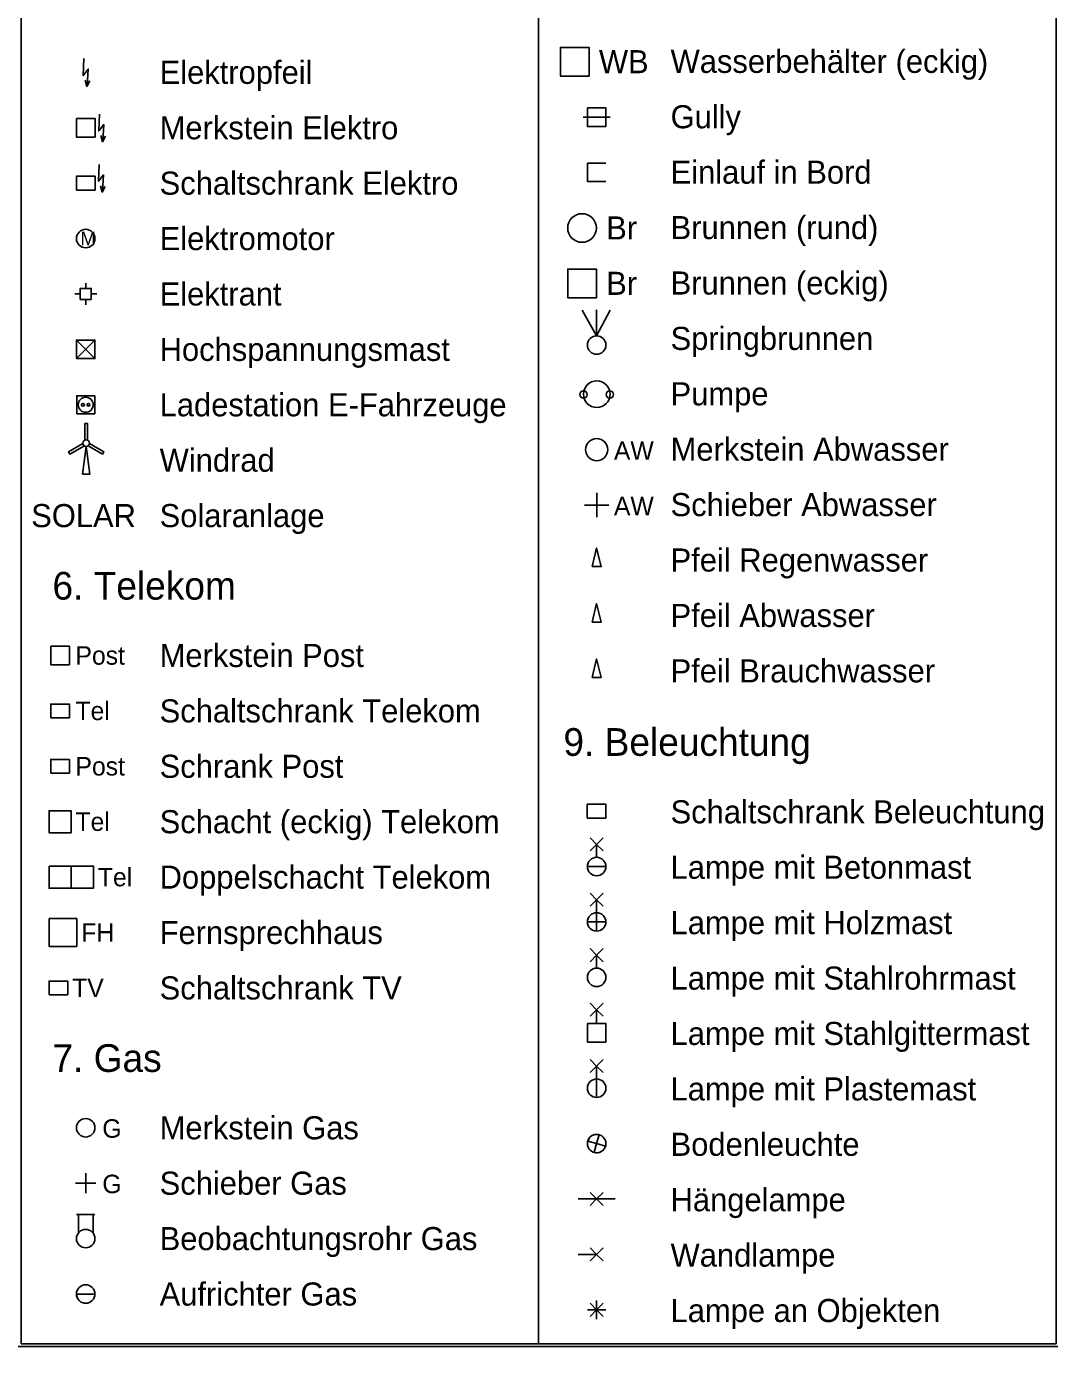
# Model space of a CAD drawing. Extents: x 679244 to 679420, y 5639809 to 5639932.
# Drawn here: x 679332.6 to 679387.9, y 5639808.5 to 5639880 of the extents above; entities that cross this region are included whole.
import ezdxf

# ---------------------------------------------------------------- set-up
doc = ezdxf.new("R2010")
doc.units = 0
for name, color, linetype in [('Aufrichter_gas', 7, 'Continuous'), ('Beobrohr_gas', 7, 'Continuous'), ('Bodenleuchte', 7, 'Continuous'), ('Brunnen_eckig', 7, 'Continuous'), ('Brunnen_rund', 7, 'Continuous'), ('Default', 7, 'Continuous'), ('Doppelschacht_tel', 7, 'Continuous'), ('Einlauf', 7, 'Continuous'), ('Elektrant', 7, 'Continuous'), ('Elektromotor', 7, 'Continuous'), ('Elektropfeil', 7, 'Continuous'), ('Fernsprechhaus', 7, 'Continuous'), ('Gully', 7, 'Continuous'), ('Haengelampe', 7, 'Continuous'), ('Hochspannungsmast', 7, 'Continuous'), ('Ladestation', 7, 'Continuous'), ('Lampe_betonmast', 7, 'Continuous'), ('Lampe_holzmast', 7, 'Continuous'), ('Lampe_plastemast', 7, 'Continuous'), ('Lampe_stahlgittermast', 7, 'Continuous'), ('Lampe_stahlrohrmast', 7, 'Continuous'), ('Merkstein_abwasser', 7, 'Continuous'), ('Merkstein_elektro', 7, 'Continuous'), ('Merkstein_gas', 7, 'Continuous'), ('Merkstein_post', 7, 'Continuous'), ('Objektlampe', 7, 'Continuous'), ('Pfeil_abwasser', 7, 'Continuous'), ('Pfeil_brauchwasser', 7, 'Continuous'), ('Pfeil_regenwasser', 7, 'Continuous'), ('Pumpe', 7, 'Continuous'), ('Rahmen_1', 7, 'Continuous'), ('Schacht_tel', 7, 'Continuous'), ('Schaltschrank_elektro', 7, 'Continuous'), ('Schaltschrank_leucht', 7, 'Continuous'), ('Schaltschrank_tel', 7, 'Continuous'), ('Schaltschrank_tv', 7, 'Continuous'), ('Schieber_abwasser', 7, 'Continuous'), ('Schieber_gas', 7, 'Continuous'), ('Schrank_post', 7, 'Continuous'), ('Schrift_aw', 7, 'Continuous'), ('Schrift_fh', 7, 'Continuous'), ('Schrift_g', 7, 'Continuous'), ('Schrift_post', 7, 'Continuous'), ('Schrift_tel', 7, 'Continuous'), ('Schrift_tv', 7, 'Continuous'), ('Schrift_wb', 7, 'Continuous'), ('Solar', 7, 'Continuous'), ('Springbrunnen', 7, 'Continuous'), ('Wandlampe', 7, 'Continuous'), ('Wasserbehaelter_eckig', 7, 'Continuous'), ('Windrad', 7, 'Continuous')]:
    doc.layers.add(name, color=color, linetype=linetype)

msp = doc.modelspace()

# ---------------------------------------------------------------- linework, layer by layer
at = {"layer": 'Aufrichter_gas'}
msp.add_lwpolyline([(679336.283, 5639811.362), (679336.282, 5639811.362), (679336.263, 5639811.362), (679335.783, 5639811.362), (679335.283, 5639811.362), (679335.283, 5639811.355)], dxfattribs=at)
msp.add_circle((679335.783, 5639811.362), 0.5, dxfattribs=at)
msp.add_arc((679335.783, 5639811.362), 0.5, 180.8, 0, dxfattribs=at)
at = {"layer": 'Beobrohr_gas'}
for p, q in [((679335.283, 5639815.664), (679336.283, 5639815.666)), ((679335.386, 5639815.664), (679335.386, 5639814.666)), ((679336.18, 5639815.666), (679336.18, 5639814.666))]:
    msp.add_line(p, q, dxfattribs=at)
msp.add_circle((679335.783, 5639814.362), 0.5, dxfattribs=at)
at = {"layer": 'Bodenleuchte'}
for points in [[(679362.945, 5639819.639), (679363.427, 5639819.506), (679363.56, 5639819.988)], [(679363.909, 5639819.373), (679363.427, 5639819.506), (679363.294, 5639819.024)]]:
    msp.add_lwpolyline(points, dxfattribs=at)
msp.add_circle((679363.427, 5639819.506), 0.5, dxfattribs=at)
for start, end in [(74.56981, 164.56981), (254.56981, 344.56981)]:
    msp.add_arc((679363.427, 5639819.506), 0.5, start, end, dxfattribs=at)
at = {"layer": 'Brunnen_eckig'}
msp.add_line((679362.635, 5639866.078), (679362.635, 5639866.078), dxfattribs=at)
msp.add_lwpolyline([(679363.41, 5639865.303), (679363.41, 5639866.853), (679361.86, 5639866.853), (679361.86, 5639865.303)], close=True, dxfattribs=at)
at = {"layer": 'Brunnen_rund'}
msp.add_line((679362.635, 5639869.078), (679362.635, 5639869.078), dxfattribs=at)
msp.add_circle((679362.635, 5639869.078), 0.775, dxfattribs=at)
at = {"layer": 'Default'}
for points in [[(679332.286, 5639808.666), (679360.286, 5639808.666), (679360.286, 5639928.666), (679332.286, 5639928.666)], [(679360.286, 5639808.666), (679388.286, 5639808.666), (679388.286, 5639928.666), (679360.286, 5639928.666)]]:
    msp.add_lwpolyline(points, close=True, dxfattribs=at)
at = {"layer": 'Doppelschacht_tel'}
for points in [[(679333.801, 5639834.534), (679335.001, 5639834.534), (679335.001, 5639833.334), (679333.801, 5639833.334)], [(679335.001, 5639834.534), (679336.201, 5639834.534), (679336.201, 5639833.334), (679335.001, 5639833.334)]]:
    msp.add_lwpolyline(points, close=True, dxfattribs=at)
at = {"layer": 'Einlauf'}
msp.add_lwpolyline([(679363.932, 5639872.587), (679362.932, 5639872.587), (679362.932, 5639871.587), (679363.932, 5639871.587)], dxfattribs=at)
at = {"layer": 'Elektrant'}
for p, q in [((679335.783, 5639866.1), (679335.783, 5639865.803)), ((679335.189, 5639865.506), (679335.486, 5639865.506)), ((679336.377, 5639865.506), (679336.08, 5639865.506)), ((679335.783, 5639864.912), (679335.783, 5639865.209))]:
    msp.add_line(p, q, dxfattribs=at)
msp.add_lwpolyline([(679336.08, 5639865.209), (679335.486, 5639865.209), (679335.486, 5639865.803), (679336.08, 5639865.803)], close=True, dxfattribs=at)
at = {"layer": 'Elektromotor'}
msp.add_circle((679335.783, 5639868.506), 0.5, dxfattribs=at)
at = {"layer": 'Elektropfeil'}
for points in [[(679335.681, 5639878.247), (679335.646, 5639877.333), (679335.92, 5639877.679), (679335.862, 5639876.785)], [(679336.01, 5639877.045), (679335.852, 5639876.748), (679335.755, 5639877.078)], [(679336.521, 5639875.247), (679336.486, 5639874.333), (679336.76, 5639874.679), (679336.702, 5639873.785)], [(679336.85, 5639874.045), (679336.692, 5639873.748), (679336.595, 5639874.078)], [(679336.511, 5639872.521), (679336.476, 5639871.607), (679336.75, 5639871.953), (679336.692, 5639871.059)], [(679336.84, 5639871.319), (679336.682, 5639871.022), (679336.585, 5639871.352)]]:
    msp.add_lwpolyline(points, dxfattribs=at)
at = {"layer": 'Fernsprechhaus'}
msp.add_lwpolyline([(679333.801, 5639831.684), (679335.301, 5639831.684), (679335.301, 5639830.184), (679333.801, 5639830.184)], close=True, dxfattribs=at)
at = {"layer": 'Gully'}
msp.add_line((679362.703, 5639875.078), (679364.15, 5639875.078), dxfattribs=at)
msp.add_lwpolyline([(679362.927, 5639875.578), (679363.927, 5639875.578), (679363.927, 5639874.578), (679362.927, 5639874.578)], close=True, dxfattribs=at)
at = {"layer": 'Haengelampe'}
for p, q in [((679363.073, 5639816.86), (679363.427, 5639816.506)), ((679363.781, 5639816.86), (679363.427, 5639816.506)), ((679363.427, 5639816.506), (679362.426, 5639816.506)), ((679363.073, 5639816.152), (679363.427, 5639816.506)), ((679363.781, 5639816.152), (679363.427, 5639816.506)), ((679364.428, 5639816.506), (679363.427, 5639816.506))]:
    msp.add_line(p, q, dxfattribs=at)
at = {"layer": 'Hochspannungsmast'}
for p, q in [((679335.283, 5639863.006), (679336.283, 5639862.006)), ((679336.283, 5639863.006), (679335.283, 5639862.006))]:
    msp.add_line(p, q, dxfattribs=at)
msp.add_lwpolyline([(679335.283, 5639862.006), (679336.283, 5639862.006), (679336.283, 5639863.006), (679335.283, 5639863.006)], close=True, dxfattribs=at)
at = {"layer": 'Ladestation'}
msp.add_lwpolyline([(679335.297, 5639859.021), (679336.268, 5639859.021), (679336.268, 5639859.992), (679335.297, 5639859.992)], close=True, dxfattribs=at)
for centre, radius in [((679335.783, 5639859.506), 0.407), ((679335.633, 5639859.506), 0.0762), ((679335.933, 5639859.506), 0.0762)]:
    msp.add_circle(centre, radius, dxfattribs=at)
at = {"layer": 'Lampe_betonmast'}
for p, q in [((679363.073, 5639836.058), (679363.427, 5639835.704)), ((679363.781, 5639836.058), (679363.427, 5639835.704)), ((679363.073, 5639835.35), (679363.427, 5639835.704)), ((679363.427, 5639835.704), (679363.427, 5639835.004)), ((679363.781, 5639835.35), (679363.427, 5639835.704))]:
    msp.add_line(p, q, dxfattribs=at)
msp.add_lwpolyline([(679363.927, 5639834.506), (679362.927, 5639834.506)], dxfattribs=at)
msp.add_circle((679363.427, 5639834.506), 0.5, dxfattribs=at)
msp.add_arc((679363.427, 5639834.506), 0.5, 180, 0, dxfattribs=at)
at = {"layer": 'Lampe_holzmast'}
for p, q in [((679363.073, 5639833.06), (679363.427, 5639832.706)), ((679363.073, 5639832.352), (679363.427, 5639832.706)), ((679363.781, 5639833.06), (679363.427, 5639832.706)), ((679363.427, 5639832.706), (679363.427, 5639832.006)), ((679363.781, 5639832.352), (679363.427, 5639832.706)), ((679363.427, 5639832.006), (679363.427, 5639831.006)), ((679362.927, 5639831.506), (679363.927, 5639831.506))]:
    msp.add_line(p, q, dxfattribs=at)
msp.add_circle((679363.427, 5639831.506), 0.5, dxfattribs=at)
at = {"layer": 'Lampe_plastemast'}
for p, q in [((679363.073, 5639824.058), (679363.427, 5639823.704)), ((679363.781, 5639824.058), (679363.427, 5639823.704)), ((679363.073, 5639823.35), (679363.427, 5639823.704)), ((679363.427, 5639823.704), (679363.427, 5639823.006)), ((679363.781, 5639823.35), (679363.427, 5639823.704))]:
    msp.add_line(p, q, dxfattribs=at)
msp.add_lwpolyline([(679363.427, 5639823.006), (679363.427, 5639822.006)], dxfattribs=at)
msp.add_circle((679363.427, 5639822.506), 0.5, dxfattribs=at)
for start, end in [(0, 90), (270, 0)]:
    msp.add_arc((679363.427, 5639822.506), 0.5, start, end, dxfattribs=at)
at = {"layer": 'Lampe_stahlgittermast'}
for p, q in [((679363.073, 5639827.11), (679363.427, 5639826.756)), ((679363.781, 5639827.11), (679363.427, 5639826.756)), ((679363.073, 5639826.402), (679363.427, 5639826.756)), ((679363.427, 5639826.756), (679363.427, 5639826.056)), ((679363.781, 5639826.402), (679363.427, 5639826.756))]:
    msp.add_line(p, q, dxfattribs=at)
msp.add_lwpolyline([(679362.927, 5639826.006), (679363.927, 5639826.006), (679363.927, 5639825.006), (679362.927, 5639825.006)], close=True, dxfattribs=at)
at = {"layer": 'Lampe_stahlrohrmast'}
for p, q in [((679363.068, 5639830.06), (679363.422, 5639829.706)), ((679363.068, 5639829.352), (679363.422, 5639829.706)), ((679363.776, 5639830.06), (679363.422, 5639829.706)), ((679363.422, 5639829.706), (679363.422, 5639829.006)), ((679363.776, 5639829.352), (679363.422, 5639829.706)), ((679363.427, 5639828.506), (679363.427, 5639828.506))]:
    msp.add_line(p, q, dxfattribs=at)
msp.add_circle((679363.427, 5639828.506), 0.5, dxfattribs=at)
at = {"layer": 'Merkstein_abwasser'}
msp.add_circle((679363.432, 5639857.078), 0.6, dxfattribs=at)
at = {"layer": 'Merkstein_elektro'}
msp.add_lwpolyline([(679335.279, 5639875.01), (679336.287, 5639875.01), (679336.286, 5639874.002), (679335.278, 5639874.002)], close=True, dxfattribs=at)
at = {"layer": 'Merkstein_gas'}
msp.add_circle((679335.783, 5639820.362), 0.5, dxfattribs=at)
at = {"layer": 'Merkstein_post'}
msp.add_lwpolyline([(679333.891, 5639846.435), (679334.899, 5639846.435), (679334.899, 5639845.427), (679333.891, 5639845.427)], close=True, dxfattribs=at)
at = {"layer": 'Objektlampe'}
for p in [(679362.926, 5639810.506), (679363.073, 5639810.86), (679363.073, 5639810.152), (679363.427, 5639811.006), (679363.781, 5639810.86), (679363.781, 5639810.152), (679363.928, 5639810.506), (679363.427, 5639810.005)]:
    msp.add_line(p, (679363.427, 5639810.506), dxfattribs=at)
at = {"layer": 'Pfeil_abwasser'}
msp.add_lwpolyline([(679363.177, 5639847.744), (679363.427, 5639848.744), (679363.677, 5639847.744)], close=True, dxfattribs=at)
at = {"layer": 'Pfeil_brauchwasser'}
msp.add_lwpolyline([(679363.177, 5639844.744), (679363.427, 5639845.744), (679363.677, 5639844.744)], close=True, dxfattribs=at)
at = {"layer": 'Pfeil_regenwasser'}
msp.add_lwpolyline([(679363.177, 5639850.744), (679363.427, 5639851.744), (679363.677, 5639850.744)], close=True, dxfattribs=at)
at = {"layer": 'Pumpe'}
for centre, radius in [((679363.432, 5639860.078), 0.721), ((679362.712, 5639860.065), 0.2), ((679364.136, 5639860.063), 0.2)]:
    msp.add_circle(centre, radius, dxfattribs=at)
at = {"layer": 'Rahmen_1'}
msp.add_lwpolyline([(679419.991, 5639808.515), (679243.507, 5639808.515), (679243.507, 5639931.667), (679419.991, 5639931.667)], close=True, dxfattribs=at)
at = {"layer": 'Schacht_tel'}
msp.add_lwpolyline([(679333.801, 5639836.34), (679334.989, 5639836.34), (679334.989, 5639837.528), (679333.801, 5639837.528)], close=True, dxfattribs=at)
at = {"layer": 'Schaltschrank_elektro'}
msp.add_lwpolyline([(679335.278, 5639871.134), (679336.287, 5639871.134), (679336.287, 5639871.878), (679335.278, 5639871.878)], close=True, dxfattribs=at)
at = {"layer": 'Schaltschrank_leucht'}
msp.add_lwpolyline([(679362.922, 5639837.134), (679363.931, 5639837.134), (679363.931, 5639837.878), (679362.922, 5639837.878)], close=True, dxfattribs=at)
at = {"layer": 'Schaltschrank_tel'}
msp.add_lwpolyline([(679333.891, 5639842.562), (679334.9, 5639842.562), (679334.9, 5639843.306), (679333.891, 5639843.306)], close=True, dxfattribs=at)
at = {"layer": 'Schaltschrank_tv'}
msp.add_lwpolyline([(679333.801, 5639827.562), (679334.81, 5639827.562), (679334.81, 5639828.306), (679333.801, 5639828.306)], close=True, dxfattribs=at)
at = {"layer": 'Schieber_abwasser'}
for q in [(679363.432, 5639854.736), (679362.773, 5639854.078), (679363.432, 5639853.419), (679364.09, 5639854.078)]:
    msp.add_line((679363.432, 5639854.078), q, dxfattribs=at)
at = {"layer": 'Schieber_gas'}
for q in [(679335.783, 5639817.911), (679335.234, 5639817.362), (679335.783, 5639816.813), (679336.332, 5639817.362)]:
    msp.add_line((679335.783, 5639817.362), q, dxfattribs=at)
at = {"layer": 'Schrank_post'}
msp.add_lwpolyline([(679333.891, 5639839.562), (679334.9, 5639839.562), (679334.9, 5639840.306), (679333.891, 5639840.306)], close=True, dxfattribs=at)
at = {"layer": 'Springbrunnen'}
for q in [(679362.638, 5639864.633), (679363.41, 5639864.639), (679364.16, 5639864.633), (679363.41, 5639863.239)]:
    msp.add_line((679363.41, 5639863.239), q, dxfattribs=at)
msp.add_circle((679363.427, 5639862.739), 0.5, dxfattribs=at)
at = {"layer": 'Wandlampe'}
for p, q in [((679363.427, 5639813.506), (679362.426, 5639813.506)), ((679363.073, 5639813.86), (679363.427, 5639813.506)), ((679363.073, 5639813.152), (679363.427, 5639813.506)), ((679363.781, 5639813.86), (679363.427, 5639813.506)), ((679363.781, 5639813.152), (679363.427, 5639813.506))]:
    msp.add_line(p, q, dxfattribs=at)
at = {"layer": 'Wasserbehaelter_eckig'}
msp.add_line((679362.242, 5639878.078), (679362.242, 5639878.078), dxfattribs=at)
msp.add_lwpolyline([(679363.017, 5639877.303), (679363.017, 5639878.853), (679361.467, 5639878.853), (679361.467, 5639877.303)], close=True, dxfattribs=at)
at = {"layer": 'Windrad'}
for p, q in [((679335.809, 5639857.256), (679335.609, 5639855.756)), ((679335.809, 5639857.256), (679336.009, 5639855.756)), ((679335.609, 5639855.756), (679336.009, 5639855.756)), ((679335.809, 5639855.756), (679335.809, 5639855.756))]:
    msp.add_line(p, q, dxfattribs=at)
for points in [[(679335.884, 5639857.589), (679335.884, 5639858.489), (679335.734, 5639858.489), (679335.734, 5639857.589)], [(679335.634, 5639857.417), (679334.855, 5639856.967), (679334.93, 5639856.837), (679335.709, 5639857.287)], [(679335.908, 5639857.287), (679336.687, 5639856.837), (679336.762, 5639856.967), (679335.983, 5639857.417)]]:
    msp.add_lwpolyline(points, dxfattribs=at)
msp.add_circle((679335.809, 5639857.431), 0.175, dxfattribs=at)
for start, end in [(64.62307, 115.37693), (184.62307, 235.37693), (304.62307, 355.37693)]:
    msp.add_arc((679335.809, 5639857.431), 0.175, start, end, dxfattribs=at)

# ---------------------------------------------------------------- texts
at = {"layer": 'Brunnen_rund'}
for p in [(679363.943, 5639868.458), (679363.943, 5639865.458)]:
    msp.add_text('Br', height=1.249, dxfattribs=at).set_placement(p)
at = {"layer": 'Default'}
for s, height, p in [('Wasserbehälter (eckig)', 1.25, (679367.427, 5639877.476)), ('Elektropfeil', 1.25, (679339.783, 5639876.881)), ('Gully', 1.25, (679367.427, 5639874.476)), ('Merkstein Elektro', 1.25, (679339.783, 5639873.881)), ('Einlauf in Bord', 1.25, (679367.427, 5639871.476)), ('Schaltschrank Elektro', 1.25, (679339.783, 5639870.881)), ('Brunnen (rund)', 1.25, (679367.427, 5639868.476)), ('Elektromotor', 1.25, (679339.783, 5639867.881)), ('Brunnen (eckig)', 1.25, (679367.427, 5639865.476)), ('Elektrant', 1.25, (679339.783, 5639864.881)), ('Springbrunnen', 1.25, (679367.427, 5639862.476)), ('Hochspannungsmast', 1.25, (679339.783, 5639861.881)), ('Pumpe', 1.25, (679367.427, 5639859.476)), ('Ladestation E-Fahrzeuge', 1.25, (679339.783, 5639858.881)), ('Merkstein Abwasser', 1.25, (679367.427, 5639856.476)), ('Windrad', 1.25, (679339.783, 5639855.881)), ('Schieber Abwasser', 1.25, (679367.427, 5639853.476)), ('Solaranlage', 1.25, (679339.783, 5639852.881)), ('Pfeil Regenwasser', 1.25, (679367.427, 5639850.476)), ('6. Telekom', 1.5, (679333.984, 5639848.958)), ('Pfeil Abwasser', 1.25, (679367.427, 5639847.476)), ('Merkstein Post', 1.25, (679339.783, 5639845.309)), ('Pfeil Brauchwasser', 1.25, (679367.427, 5639844.476)), ('Schaltschrank Telekom', 1.25, (679339.783, 5639842.309)), ('9. Beleuchtung', 1.5, (679361.628, 5639840.499)), ('Schrank Post', 1.25, (679339.783, 5639839.309)), ('Schacht (eckig) Telekom', 1.25, (679339.783, 5639836.309)), ('Schaltschrank Beleuchtung', 1.25, (679367.427, 5639836.843)), ('Lampe mit Betonmast', 1.25, (679367.427, 5639833.843)), ('Doppelschacht Telekom', 1.25, (679339.783, 5639833.309)), ('Lampe mit Holzmast', 1.25, (679367.427, 5639830.843)), ('Fernsprechhaus', 1.25, (679339.783, 5639830.309)), ('Lampe mit Stahlrohrmast', 1.25, (679367.427, 5639827.843)), ('Schaltschrank TV', 1.25, (679339.783, 5639827.309)), ('Lampe mit Stahlgittermast', 1.25, (679367.427, 5639824.843)), ('7. Gas', 1.5, (679333.984, 5639823.386)), ('Lampe mit Plastemast', 1.25, (679367.427, 5639821.843)), ('Merkstein Gas', 1.25, (679339.783, 5639819.737)), ('Bodenleuchte', 1.25, (679367.427, 5639818.843)), ('Schieber Gas', 1.25, (679339.783, 5639816.737)), ('Hängelampe', 1.25, (679367.427, 5639815.843)), ('Beobachtungsrohr Gas', 1.25, (679339.783, 5639813.737)), ('Wandlampe', 1.25, (679367.427, 5639812.843)), ('Aufrichter Gas', 1.25, (679339.783, 5639810.737)), ('Lampe an Objekten', 1.25, (679367.427, 5639809.843))]:
    msp.add_text(s, height=height, dxfattribs=at).set_placement(p)
at = {"layer": 'Elektromotor'}
msp.add_text('M', height=0.75, dxfattribs=at).set_placement((679335.496, 5639868.131))
at = {"layer": 'Schrift_aw'}
for p in [(679364.362, 5639856.526), (679364.362, 5639853.526)]:
    msp.add_text('AW', height=1, dxfattribs=at).set_placement(p)
at = {"layer": 'Schrift_fh'}
msp.add_text('FH', height=1, dxfattribs=at).set_placement((679335.541, 5639830.435))
at = {"layer": 'Schrift_g'}
for p in [(679336.682, 5639819.822), (679336.682, 5639816.822)]:
    msp.add_text('G', height=1, dxfattribs=at).set_placement(p)
at = {"layer": 'Schrift_post'}
for p in [(679335.229, 5639845.435), (679335.229, 5639839.435)]:
    msp.add_text('Post', height=1, dxfattribs=at).set_placement(p)
at = {"layer": 'Schrift_tel'}
for p in [(679335.229, 5639842.435), (679335.229, 5639836.435), (679336.441, 5639833.435)]:
    msp.add_text('Tel', height=1, dxfattribs=at).set_placement(p)
at = {"layer": 'Schrift_tv'}
msp.add_text('TV', height=1, dxfattribs=at).set_placement((679335.05, 5639827.435))
at = {"layer": 'Schrift_wb'}
msp.add_text('WB', height=1.249, dxfattribs=at).set_placement((679363.55, 5639877.458))
at = {"layer": 'Solar'}
msp.add_text('SOLAR', height=1.25, dxfattribs=at).set_placement((679332.834, 5639852.881))

doc.saveas('drawing.dxf')
